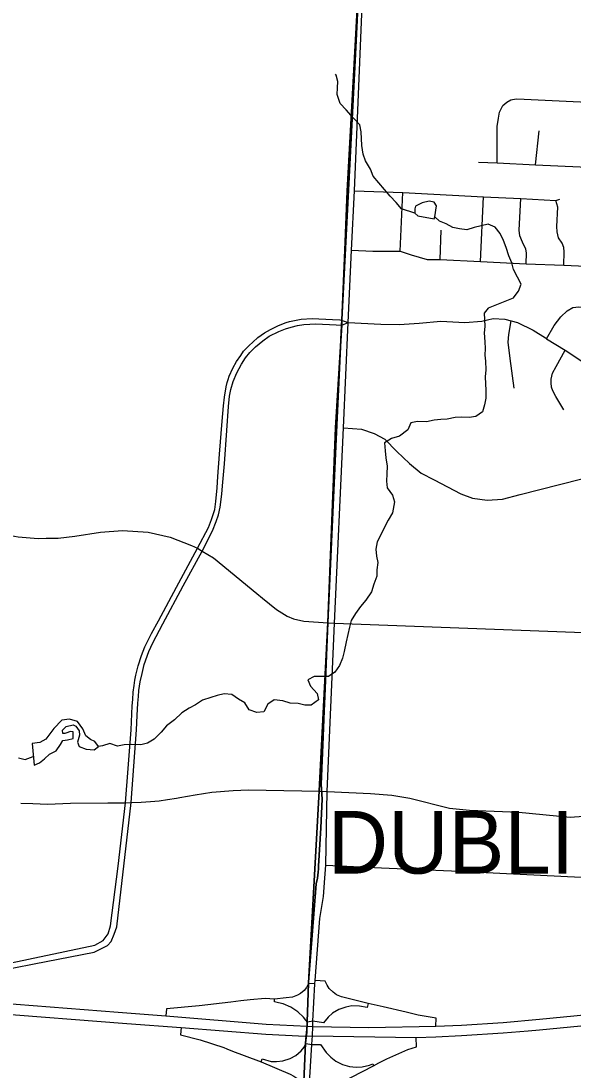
# Model space of a CAD drawing. Extents: x 0 to 34, y 0 to 22.
# Drawn here: x 14.81 to 15.645, y 6.384 to 7.972 of the extents above; entities that cross this region are included whole.
import ezdxf

# ---------------------------------------------------------------- set-up
doc = ezdxf.new("R2010")
doc.units = 0
for name, color, linetype in [('GM_X_City_Street', 7, 'Continuous'), ('GM_X_Corporation', 7, 'Continuous'), ('GM_X_Corporation_Text', 7, 'Continuous'), ('GM_X_County_Road', 7, 'Continuous'), ('GM_X_Interchange_Ramps', 7, 'Continuous'), ('GM_X_Interstate_Route', 7, 'Continuous'), ('GM_X_Minor_Lake', 7, 'Continuous'), ('GM_X_Minor_River', 7, 'Continuous')]:
    doc.layers.add(name, color=color, linetype=linetype)

msp = doc.modelspace()

# ---------------------------------------------------------------- linework, layer by layer
at = {"layer": 'GM_X_City_Street'}
for p, q in [((15.5886, 7.7545), (15.594, 7.8058)), ((15.3838, 7.6239), (15.3877, 7.7123)), ((15.5051, 7.6079), (15.51, 7.7058)), ((15.4443, 7.6112), (15.446, 7.6555))]:
    msp.add_line(p, q, dxfattribs=at)
for points in [[(15.2845, 7.0608), (15.2979, 7.3561), (15.3048, 7.5157), (15.3102, 7.6252), (15.3146, 7.7151), (15.3266, 8.0075), (15.3312, 8.1027), (15.34, 8.2816), (15.3508, 8.5062), (15.3476, 8.5296)], [(15.5304, 7.7573), (15.5305, 7.8123), (15.5325, 7.8249), (15.5341, 7.8343), (15.539, 7.8443), (15.5453, 7.8491), (15.551, 7.8529), (15.5593, 7.8544), (15.5714, 7.8537), (15.7307, 7.8461)], [(15.5022, 7.7586), (15.5304, 7.7573), (15.5886, 7.7545), (15.656, 7.7513), (15.7278, 7.7479)], [(15.3146, 7.7151), (15.3877, 7.7123), (15.51, 7.7058), (15.5666, 7.7033), (15.6193, 7.7005), (15.6256, 7.7023)], [(15.5746, 7.6047), (15.5748, 7.621), (15.574, 7.6267), (15.5688, 7.6375), (15.5649, 7.6468), (15.5639, 7.6553), (15.5666, 7.7033)], [(15.6313, 7.6024), (15.632, 7.6225), (15.6315, 7.629), (15.6289, 7.636), (15.6233, 7.644), (15.6212, 7.6527), (15.6209, 7.661), (15.6225, 7.6901), (15.6193, 7.7005)], [(15.3102, 7.6252), (15.3425, 7.6239), (15.3838, 7.6239)], [(15.3838, 7.6239), (15.4002, 7.6182), (15.4244, 7.6111), (15.4443, 7.6112), (15.5051, 7.6079), (15.5746, 7.6047), (15.6313, 7.6024), (15.6875, 7.5998), (15.6875, 7.6094), (15.688, 7.6233)], [(15.6054, 7.4912), (15.6168, 7.5113), (15.6267, 7.5244), (15.6363, 7.5335), (15.645, 7.5383), (15.6541, 7.5393), (15.6639, 7.5389), (15.6733, 7.5374), (15.6804, 7.5341), (15.6911, 7.5228), (15.7034, 7.5091), (15.7455, 7.4618)], [(14.9768, 6.8993), (14.9782, 6.9356), (14.9789, 6.9453), (14.9798, 6.9564), (14.9811, 6.9661), (14.9823, 6.9746), (14.9839, 6.9822), (14.9874, 6.9959), (14.9922, 7.0117), (14.9975, 7.025), (15.0074, 7.0451), (15.0178, 7.0643), (15.045, 7.1152), (15.0768, 7.174), (15.0934, 7.2053), (15.0984, 7.2176), (15.103, 7.2326), (15.1047, 7.245), (15.107, 7.2654), (15.1078, 7.2826), (15.1104, 7.3163), (15.1145, 7.3664), (15.1165, 7.3895), (15.1177, 7.4028), (15.1202, 7.4184), (15.1221, 7.4251), (15.1234, 7.4297), (15.1251, 7.4345), (15.1305, 7.4464), (15.1361, 7.4566), (15.1426, 7.466), (15.1468, 7.4722), (15.1553, 7.4809), (15.1607, 7.486), (15.1683, 7.4928), (15.1782, 7.5), (15.1873, 7.505), (15.1984, 7.5107), (15.2046, 7.5132), (15.2112, 7.5156), (15.2161, 7.5172), (15.2238, 7.519), (15.2337, 7.5207), (15.2503, 7.5217), (15.2811, 7.5204), (15.2924, 7.5197), (15.2959, 7.5186), (15.3048, 7.5157)], [(14.9849, 6.8993), (14.9856, 6.9208), (14.9869, 6.9395), (14.9876, 6.9498), (14.9884, 6.9589), (14.9903, 6.9717), (14.993, 6.9845), (14.9965, 6.998), (15.0033, 7.0178), (15.0092, 7.0308), (15.0244, 7.0596), (15.0551, 7.1173), (15.0842, 7.1698), (15.0997, 7.2005), (15.1054, 7.2144), (15.1089, 7.2245), (15.1113, 7.236), (15.1139, 7.2561), (15.1148, 7.2685), (15.1178, 7.3017), (15.1216, 7.3525), (15.1237, 7.3886), (15.1256, 7.4041), (15.1275, 7.4144), (15.1311, 7.4264), (15.1363, 7.4396), (15.1434, 7.4527), (15.1497, 7.462), (15.1564, 7.4705), (15.1649, 7.4789), (15.1757, 7.4881), (15.1856, 7.4949), (15.2001, 7.5022), (15.21, 7.5061), (15.2186, 7.5089), (15.2282, 7.5111), (15.238, 7.5127), (15.2563, 7.5136), (15.287, 7.5123), (15.2956, 7.5117), (15.3048, 7.5157)], [(15.3048, 7.5157), (15.3545, 7.513), (15.3821, 7.5126), (15.4127, 7.5147), (15.4453, 7.5177), (15.4816, 7.5156), (15.5071, 7.5176), (15.5243, 7.5218), (15.5421, 7.521), (15.5516, 7.5184), (15.5613, 7.5158), (15.5848, 7.5041), (15.6036, 7.4924), (15.6054, 7.4912), (15.6333, 7.4736), (15.6466, 7.4651), (15.712, 7.4207)], [(15.5564, 7.4165), (15.5502, 7.4612), (15.5472, 7.4862), (15.548, 7.4976), (15.5516, 7.5184)], [(15.6317, 7.3833), (15.6191, 7.4038), (15.6148, 7.4122), (15.6126, 7.4178), (15.6121, 7.4245), (15.6123, 7.4301), (15.6142, 7.4389), (15.6197, 7.4492), (15.6333, 7.4736)], [(15.2979, 7.3561), (15.325, 7.3543), (15.3443, 7.3478), (15.3605, 7.339), (15.3789, 7.3206), (15.3978, 7.3022), (15.4157, 7.2877), (15.435, 7.2777), (15.4758, 7.2566), (15.4933, 7.2501), (15.5156, 7.247), (15.5384, 7.2483), (15.5656, 7.2553), (15.6866, 7.286)], [(15.271, 6.6942), (15.2733, 6.8061), (15.2845, 7.0608)], [(14.2174, 6.5112), (14.4156, 6.5276), (14.5716, 6.5315), (14.7466, 6.5398), (14.7753, 6.5424), (14.9218, 6.5734), (14.9343, 6.5802), (14.9417, 6.5906), (14.9451, 6.6027), (14.9567, 6.6929), (14.9678, 6.7887), (14.9768, 6.8993)], [(14.2188, 6.5021), (14.4306, 6.5183), (14.5865, 6.5222), (14.7678, 6.5327), (14.83, 6.5453), (14.9206, 6.5627), (14.9409, 6.5726), (14.9463, 6.5788), (14.9509, 6.5899), (14.955, 6.6012), (14.9768, 6.7893), (14.9849, 6.8993)], [(14.8096, 6.7884), (14.8276, 6.7875), (14.85, 6.7869), (14.8848, 6.7881), (14.9411, 6.7887), (14.9678, 6.7887), (14.9768, 6.7893), (14.9915, 6.7897), (15.0061, 6.7906), (15.019, 6.7919), (15.0315, 6.7937), (15.0451, 6.7957), (15.05, 6.7967), (15.0737, 6.801), (15.0988, 6.8048), (15.1311, 6.8074), (15.1542, 6.8084), (15.181, 6.8078), (15.2614, 6.8064), (15.2733, 6.8061)], [(15.2733, 6.8061), (15.339, 6.8029), (15.3709, 6.8003), (15.3986, 6.7956), (15.4582, 6.7806), (15.4889, 6.7774), (15.5635, 6.7748), (15.6411, 6.7672), (15.6747, 6.7695)], [(15.2551, 6.5196), (15.2623, 6.6139), (15.2675, 6.6471), (15.2695, 6.6749), (15.271, 6.6942)], [(15.271, 6.6942), (15.3556, 6.6904), (15.4728, 6.6854), (15.6887, 6.6749), (15.8608, 6.6645), (16.0183, 6.657), (16.1405, 6.6512)], [(15.2506, 6.4301), (15.251, 6.4363), (15.2514, 6.4503), (15.2514, 6.4582), (15.2545, 6.5148), (15.2551, 6.5196)], [(15.2445, 6.3411), (15.2461, 6.3564), (15.2502, 6.4231), (15.2506, 6.4301)]]:
    msp.add_lwpolyline(points, dxfattribs=at)
at = {"layer": 'GM_X_Corporation'}
for points in [[(15.1992, 5.3985), (15.201, 5.4494), (15.2071, 5.6208), (15.2073, 5.629), (15.2168, 5.7913), (15.2222, 5.883), (15.2243, 5.9546), (15.2312, 6.215), (15.2374, 6.3555), (15.2406, 6.4249), (15.2417, 6.4361), (15.243, 6.4513), (15.2431, 6.4575), (15.2449, 6.5158), (15.2612, 6.8069), (15.2745, 7.0618), (15.2858, 7.3562), (15.2954, 7.5122), (15.2956, 7.5191), (15.3002, 7.6254), (15.3034, 7.7146), (15.3197, 8.0084)], [(15.3197, 8.0084), (15.3034, 7.7146), (15.3002, 7.6254), (15.2956, 7.5191), (15.2954, 7.5122), (15.2858, 7.3562), (15.2745, 7.0618), (15.2612, 6.8069), (15.2449, 6.5158), (15.2431, 6.4575), (15.243, 6.4513), (15.2417, 6.4361), (15.2406, 6.4249), (15.2374, 6.3555), (15.2312, 6.215), (15.2243, 5.9546), (15.2222, 5.883), (15.2168, 5.7913), (15.2073, 5.629), (15.2071, 5.6208), (15.201, 5.4494), (15.1992, 5.3985)], [(15.2374, 6.3555), (15.2406, 6.4249), (15.2423, 6.4418), (15.2431, 6.4575), (15.2449, 6.5158), (15.2567, 6.666), (15.2586, 6.6749), (15.2598, 6.6839), (15.2601, 6.6888), (15.2602, 6.6929), (15.2635, 6.7509), (15.2659, 6.7944), (15.2643, 6.8172), (15.2668, 6.8766), (15.2687, 6.9279), (15.2696, 6.9496), (15.2744, 7.0607), (15.286, 7.3174), (15.2943, 7.5007), (15.3168, 7.9317), (15.3196, 7.9939)], [(15.3196, 7.9939), (15.3168, 7.9317), (15.2943, 7.5007), (15.286, 7.3174), (15.2744, 7.061), (15.2696, 6.9496), (15.2687, 6.9279), (15.2668, 6.8766), (15.2643, 6.8172), (15.2659, 6.7944), (15.2635, 6.7509), (15.2602, 6.6929), (15.2601, 6.6888), (15.2598, 6.6839), (15.2586, 6.6749), (15.2567, 6.666), (15.2451, 6.5171), (15.2431, 6.4578), (15.2423, 6.4418), (15.2406, 6.4249), (15.2374, 6.3555)]]:
    msp.add_lwpolyline(points, dxfattribs=at)
at = {"layer": 'GM_X_County_Road'}
msp.add_line((15.2747, 7.0613), (15.2845, 7.0608), dxfattribs=at)
for points in [[(14.2649, 7.2806), (14.3127, 7.2806), (14.3304, 7.2792), (14.3482, 7.2765), (14.3717, 7.27), (14.4151, 7.2547), (14.4366, 7.2468), (14.4557, 7.2427), (14.4739, 7.2412), (14.6413, 7.2397), (14.6586, 7.2391), (14.673, 7.2367), (14.6897, 7.2311), (14.7125, 7.2201), (14.7274, 7.2131), (14.75, 7.2041), (14.7757, 7.1967), (14.7947, 7.1931), (14.8054, 7.1911), (14.836, 7.189), (14.8481, 7.1892)], [(14.8481, 7.1892), (14.8663, 7.1895), (14.8911, 7.1923), (14.9302, 7.1984), (14.9637, 7.2009), (15.0023, 7.1982), (15.0358, 7.1908), (15.0678, 7.1781), (15.0768, 7.174), (15.0842, 7.1698), (15.1011, 7.1596), (15.1668, 7.1055), (15.1753, 7.0986)], [(15.1753, 7.0986), (15.1968, 7.0811), (15.2126, 7.0711), (15.2225, 7.0673), (15.2381, 7.0637), (15.2747, 7.0613)], [(15.2845, 7.0608), (15.8092, 7.041), (15.8146, 7.0408)]]:
    msp.add_lwpolyline(points, dxfattribs=at)
at = {"layer": 'GM_X_Interchange_Ramps'}
for points in [[(15.2441, 6.5132), (15.2419, 6.5091), (15.2382, 6.5047), (15.233, 6.5002), (15.2282, 6.4975), (15.2209, 6.4948), (15.2114, 6.4934), (15.1936, 6.4915)], [(15.2545, 6.5148), (15.2452, 6.5153), (15.2441, 6.5132)], [(15.3352, 6.4849), (15.2948, 6.4953), (15.2875, 6.4983), (15.2821, 6.502), (15.2765, 6.5077), (15.2732, 6.5126), (15.27, 6.5188), (15.2551, 6.5196)], [(15.1425, 6.4889), (15.1273, 6.4872), (15.0795, 6.4813), (15.03, 6.4767), (15.0293, 6.4664)], [(15.1936, 6.4915), (15.1795, 6.4925), (15.1567, 6.4905), (15.1425, 6.4889)], [(15.2411, 6.4598), (15.2373, 6.4645), (15.2287, 6.4724), (15.2182, 6.4796), (15.2066, 6.4845), (15.1995, 6.4862), (15.1934, 6.4873), (15.1936, 6.4915)], [(15.3352, 6.4849), (15.3336, 6.4788), (15.3223, 6.481), (15.3104, 6.4813), (15.3015, 6.4796), (15.291, 6.4759), (15.2813, 6.4705), (15.2746, 6.4645), (15.2677, 6.4557), (15.2514, 6.4582)], [(15.3989, 6.4705), (15.3927, 6.4721), (15.3582, 6.4801), (15.3352, 6.4849)], [(15.4378, 6.4505), (15.4384, 6.4627), (15.4111, 6.4673), (15.3989, 6.4705)], [(15.0523, 6.4485), (15.0515, 6.4376), (15.0808, 6.43), (15.1166, 6.4183), (15.1215, 6.4164)], [(15.2514, 6.4582), (15.2433, 6.457), (15.2411, 6.4598)], [(15.3436, 6.3905), (15.3513, 6.395), (15.3637, 6.4013), (15.3819, 6.4095), (15.3954, 6.4154), (15.4085, 6.4193), (15.408, 6.4338)], [(15.1215, 6.4164), (15.13, 6.4131), (15.1477, 6.4065), (15.1735, 6.3968)], [(15.1735, 6.3968), (15.1751, 6.4011), (15.1885, 6.3974), (15.1966, 6.3971), (15.2063, 6.3984), (15.2174, 6.4017), (15.226, 6.4065), (15.2338, 6.4133), (15.2384, 6.4187), (15.24, 6.4224)], [(15.24, 6.4224), (15.2408, 6.4243), (15.2502, 6.4231)], [(15.2502, 6.4231), (15.2632, 6.4228), (15.2719, 6.4111), (15.2789, 6.4036), (15.2864, 6.3976), (15.2964, 6.3928), (15.3072, 6.3895), (15.3171, 6.3888), (15.3261, 6.389), (15.3372, 6.3915), (15.3425, 6.3937), (15.3436, 6.3905)], [(15.1735, 6.3968), (15.2172, 6.3781), (15.2229, 6.3751), (15.2274, 6.3718), (15.2316, 6.3679), (15.2358, 6.3609), (15.2369, 6.3574)], [(15.2445, 6.3411), (15.2604, 6.3405), (15.2665, 6.3482), (15.2708, 6.3526), (15.277, 6.3563), (15.3436, 6.3905)]]:
    msp.add_lwpolyline(points, dxfattribs=at)
at = {"layer": 'GM_X_Interstate_Route'}
for points in [[(15.4378, 6.4505), (15.4766, 6.4524), (15.5394, 6.4562), (15.5944, 6.4613), (15.7606, 6.4773), (15.9026, 6.4904), (16.072, 6.5065), (16.2243, 6.52), (16.4666, 6.5435), (16.5962, 6.5553), (16.8997, 6.5836), (17.0352, 6.5966), (17.2219, 6.6135), (17.462, 6.6358), (17.6245, 6.6514), (17.6868, 6.6559), (17.7405, 6.6589), (17.7919, 6.6602), (17.8264, 6.6611), (17.8341, 6.6611), (17.8732, 6.6603), (17.9712, 6.6585), (18.0404, 6.6575)], [(13.9741, 6.4304), (13.9917, 6.4333), (14.1837, 6.4635), (14.257, 6.4743), (14.3176, 6.4815), (14.3823, 6.4874), (14.4479, 6.4918), (14.5306, 6.4949), (14.6071, 6.4945), (14.6751, 6.4925), (14.7505, 6.4879), (14.9569, 6.4719), (15.0293, 6.4664), (15.1808, 6.4536), (15.2432, 6.4507), (15.2514, 6.4503), (15.3365, 6.4486), (15.4378, 6.4505)], [(14.1107, 6.4358), (14.1196, 6.4372), (14.1817, 6.4472), (14.2688, 6.4597), (14.3603, 6.47), (14.4326, 6.4748), (14.5353, 6.4785), (14.6171, 6.4779), (14.6866, 6.4761), (14.7623, 6.4709), (14.9702, 6.4548), (15.0523, 6.4485), (15.1806, 6.4384), (15.24, 6.4356)], [(15.24, 6.4356), (15.2419, 6.4355), (15.251, 6.4363), (15.408, 6.4338), (15.4378, 6.4347), (15.4766, 6.4366), (15.5394, 6.4404), (15.5774, 6.4438), (15.5944, 6.4454), (15.7665, 6.4618)]]:
    msp.add_lwpolyline(points, dxfattribs=at)
at = {"layer": 'GM_X_Minor_Lake'}
for points in [[(15.4364, 7.6756), (15.4387, 7.6923), (15.435, 7.698), (15.4274, 7.6992), (15.4172, 7.697), (15.4069, 7.6917), (15.4058, 7.6876), (15.4058, 7.6811), (15.4103, 7.6773)], [(15.4103, 7.6773), (15.4353, 7.6725), (15.4364, 7.6756)], [(14.8298, 6.8456), (14.8379, 6.8492), (14.8455, 6.8552), (14.8532, 6.8623), (14.8631, 6.8675), (14.8697, 6.8769), (14.8732, 6.8829), (14.8804, 6.8843), (14.8888, 6.8861), (14.8889, 6.8964), (14.8844, 6.8968), (14.8805, 6.895), (14.876, 6.8939), (14.8733, 6.8939), (14.8726, 6.8989), (14.878, 6.9041), (14.889, 6.9066), (14.8928, 6.905), (14.898, 6.8978), (14.8983, 6.8913), (14.8955, 6.8807), (14.8981, 6.8738), (14.9083, 6.8702), (14.9204, 6.8689), (14.9269, 6.8738), (14.9217, 6.8818), (14.9149, 6.8846), (14.9081, 6.89), (14.9034, 6.9007), (14.8956, 6.9118), (14.8831, 6.9154), (14.8717, 6.9141), (14.8594, 6.901), (14.8474, 6.8852), (14.8386, 6.88), (14.8265, 6.8783)], [(14.8265, 6.8783), (14.8298, 6.8456)]]:
    msp.add_lwpolyline(points, dxfattribs=at)
at = {"layer": 'GM_X_Minor_River'}
for points in [[(15.4059, 7.681), (15.3857, 7.6877), (15.3778, 7.6972), (15.3684, 7.7068), (15.3602, 7.7171), (15.3515, 7.727), (15.3429, 7.7373), (15.3388, 7.7476), (15.3313, 7.7602), (15.3275, 7.7705), (15.3257, 7.7834), (15.3247, 7.8043), (15.3229, 7.8149), (15.3131, 7.8252), (15.3018, 7.8378), (15.2928, 7.8474), (15.2883, 7.8607), (15.2887, 7.8709), (15.2896, 7.8804), (15.287, 7.8903), (15.2858, 7.8914)], [(15.5549, 7.5526), (15.5629, 7.5632), (15.5671, 7.5738), (15.5615, 7.5844), (15.5555, 7.5959), (15.5525, 7.6061), (15.5484, 7.6168), (15.5443, 7.629), (15.5399, 7.6396), (15.535, 7.6503), (15.5275, 7.6598), (15.5169, 7.6648), (15.5063, 7.6619), (15.4957, 7.6593), (15.4847, 7.6559), (15.4734, 7.6575), (15.4635, 7.6595), (15.4533, 7.6649), (15.4435, 7.6691), (15.4364, 7.6756)], [(15.5549, 7.5526), (15.5167, 7.5372), (15.5107, 7.53), (15.5113, 7.5201), (15.5119, 7.5098), (15.511, 7.5), (15.512, 7.4867), (15.5122, 7.4764), (15.5121, 7.4665), (15.5131, 7.457), (15.5133, 7.4441), (15.5124, 7.4335), (15.5127, 7.4228), (15.5133, 7.4133), (15.5135, 7.4012), (15.5115, 7.3909), (15.5083, 7.3803), (15.4984, 7.3737), (15.4881, 7.3719), (15.4763, 7.3725), (15.4669, 7.3718), (15.4547, 7.3694), (15.4452, 7.3691), (15.4353, 7.3678), (15.4236, 7.3656), (15.4099, 7.3658), (15.4001, 7.3641), (15.3954, 7.3531), (15.3827, 7.3435), (15.3705, 7.3402), (15.3602, 7.3335), (15.3612, 7.3214), (15.3618, 7.3111), (15.3643, 7.2981), (15.3638, 7.2867), (15.3632, 7.2757), (15.3642, 7.2655), (15.372, 7.2543), (15.3753, 7.2444), (15.3721, 7.2277), (15.3655, 7.2164), (15.3596, 7.2051), (15.3546, 7.1946), (15.3491, 7.1836), (15.3471, 7.1726), (15.3477, 7.162), (15.3498, 7.1525), (15.3482, 7.1415), (15.3484, 7.132), (15.3441, 7.1195), (15.3405, 7.1081), (15.3316, 7.0957), (15.3236, 7.086), (15.3162, 7.0755), (15.3096, 7.0649), (15.3068, 7.0547), (15.3044, 7.0437), (15.302, 7.0324), (15.2991, 7.018), (15.2967, 7.0077), (15.292, 6.9964), (15.2847, 6.9863), (15.2751, 6.9799), (15.2653, 6.9801), (15.2535, 6.9799), (15.244, 6.9747), (15.248, 6.9651), (15.2581, 6.9544), (15.2599, 6.9445), (15.2488, 6.9366), (15.2393, 6.9364), (15.2295, 6.9392), (15.217, 6.9394), (15.206, 6.943), (15.1932, 6.9447), (15.1836, 6.938), (15.1774, 6.9267), (15.1667, 6.9253), (15.1554, 6.9297), (15.1488, 6.94), (15.139, 6.9455), (15.1292, 6.9525), (15.1175, 6.9538), (15.1068, 6.9513), (15.0973, 6.9484), (15.0844, 6.944), (15.074, 6.9373), (15.0645, 6.9321), (15.0534, 6.9247), (15.0423, 6.9142), (15.03, 6.9053), (15.0219, 6.8955), (15.0116, 6.8851), (15.0012, 6.8791), (14.991, 6.8766), (14.9766, 6.8768), (14.966, 6.8766), (14.9561, 6.8745), (14.9444, 6.8784), (14.9333, 6.8748), (14.9269, 6.8738)], [(14.8061, 6.8569), (14.8163, 6.8545), (14.8285, 6.8587)]]:
    msp.add_lwpolyline(points, dxfattribs=at)

# ---------------------------------------------------------------- texts
at = {"layer": 'GM_X_Corporation_Text'}
msp.add_text('DUBLIN', height=0.0947, rotation=0, dxfattribs=at).set_placement((15.274, 6.6817))

doc.saveas('drawing.dxf')
